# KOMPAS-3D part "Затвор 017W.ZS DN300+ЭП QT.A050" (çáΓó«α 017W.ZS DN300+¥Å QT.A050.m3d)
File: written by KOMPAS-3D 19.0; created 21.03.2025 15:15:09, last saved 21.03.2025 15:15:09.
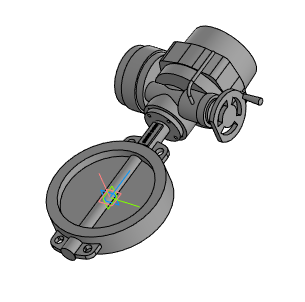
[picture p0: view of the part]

Document properties: Полное имя файла: Затвор 017W.ZS DN300+ЭП QT.A050.a3d

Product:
- Part/product: Затвор 017W.ZS DN300+ЭП QT.A050
    Масса: 153.072

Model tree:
1. Операция без истории:1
